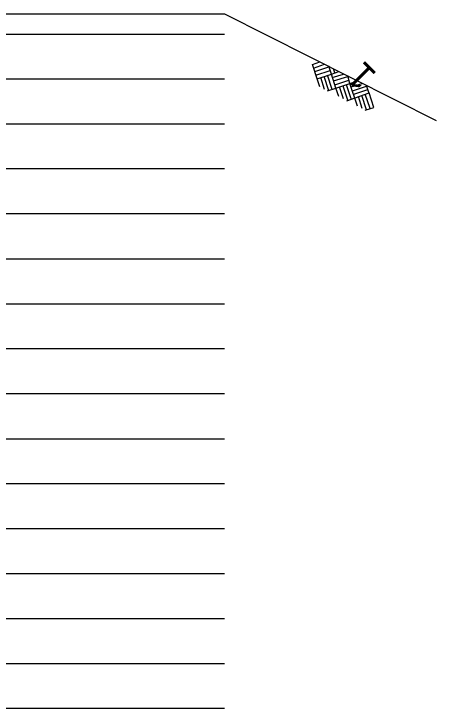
# Model space of a CAD drawing. Extents: x -0.04 to 2.79, y -0.02 to 1.81.
# Drawn here: x 1.512 to 1.5793, y 1.0349 to 1.1454 of the extents above; entities that cross this region are included whole.
import ezdxf

# ---------------------------------------------------------------- set-up
doc = ezdxf.new("R2010")
doc.units = 0
doc.layers.add('Level 1', color=7, linetype='Continuous')

msp = doc.modelspace()

# ---------------------------------------------------------------- linework, layer by layer
at = {"layer": 'Level 1'}
for p, q in [((1.46607, 1.14538), (1.54556, 1.14538)), ((1.54556, 1.14538), (1.57926, 1.12843)), ((1.46716, 1.14217), (1.54556, 1.14217)), ((1.55957, 1.13732), (1.56074, 1.13773)), ((1.56033, 1.13506), (1.55957, 1.13732)), ((1.55971, 1.13677), (1.56149, 1.13738)), ((1.55992, 1.13622), (1.56217, 1.13697)), ((1.56258, 1.13581), (1.56217, 1.13704)), ((1.56313, 1.13602), (1.56292, 1.13663)), ((1.56012, 1.13561), (1.56238, 1.13636)), ((1.56033, 1.13506), (1.56258, 1.13581)), ((1.56272, 1.13335), (1.56197, 1.13561)), ((1.56258, 1.13581), (1.56374, 1.13622)), ((1.56258, 1.13581), (1.56374, 1.13622)), ((1.56327, 1.13356), (1.56258, 1.13581)), ((1.56272, 1.13526), (1.5645, 1.13581)), ((1.56368, 1.13615), (1.56368, 1.13629)), ((1.56552, 1.13431), (1.56518, 1.13554)), ((1.46716, 1.13506), (1.54556, 1.13506)), ((1.56074, 1.13376), (1.56033, 1.13506)), ((1.56149, 1.13335), (1.56087, 1.13526)), ((1.56217, 1.13315), (1.56142, 1.1354)), ((1.56292, 1.13472), (1.56518, 1.1354)), ((1.56313, 1.1341), (1.56538, 1.13485)), ((1.56552, 1.13431), (1.56675, 1.13472)), ((1.56552, 1.13431), (1.56675, 1.13472)), ((1.56197, 1.13315), (1.56327, 1.13356)), ((1.56327, 1.13356), (1.56552, 1.13431)), ((1.56374, 1.13226), (1.56327, 1.13356)), ((1.5645, 1.13185), (1.56388, 1.13376)), ((1.56518, 1.13164), (1.56443, 1.1339)), ((1.56573, 1.13185), (1.56497, 1.1341)), ((1.56675, 1.13069), (1.56552, 1.13431)), ((1.56573, 1.13376), (1.5675, 1.13431)), ((1.56593, 1.13315), (1.56819, 1.1339)), ((1.56614, 1.1326), (1.56839, 1.13335)), ((1.5686, 1.13274), (1.56819, 1.13397)), ((1.56634, 1.13205), (1.5686, 1.1328)), ((1.5675, 1.13034), (1.56689, 1.13226)), ((1.56819, 1.13014), (1.56744, 1.13239)), ((1.56873, 1.13034), (1.56798, 1.1326)), ((1.56935, 1.13048), (1.5686, 1.1328)), ((1.56504, 1.13157), (1.56634, 1.13205)), ((1.56798, 1.13007), (1.56935, 1.13048)), ((1.46716, 1.12788), (1.54556, 1.12788)), ((1.46716, 1.12077), (1.54556, 1.12077)), ((1.46716, 1.1136), (1.54556, 1.1136)), ((1.46716, 1.10642), (1.54556, 1.10642)), ((1.46716, 1.09924), (1.54556, 1.09924)), ((1.46716, 1.09214), (1.54556, 1.09214)), ((1.46716, 1.08496), (1.54556, 1.08496)), ((1.46716, 1.07778), (1.54556, 1.07778)), ((1.46716, 1.07067), (1.54556, 1.07067)), ((1.46716, 1.0635), (1.54556, 1.0635)), ((1.46716, 1.05632), (1.54556, 1.05632)), ((1.46716, 1.04921), (1.54556, 1.04921)), ((1.46716, 1.04203), (1.54556, 1.04203)), ((1.46716, 1.03493), (1.54556, 1.03493))]:
    msp.add_line(p, q, dxfattribs=at)

# ---------------------------------------------------------------- texts
msp.add_text('1', height=0.00424, rotation=135, dxfattribs=at).set_placement((1.56996, 1.13581))

doc.saveas('drawing.dxf')
